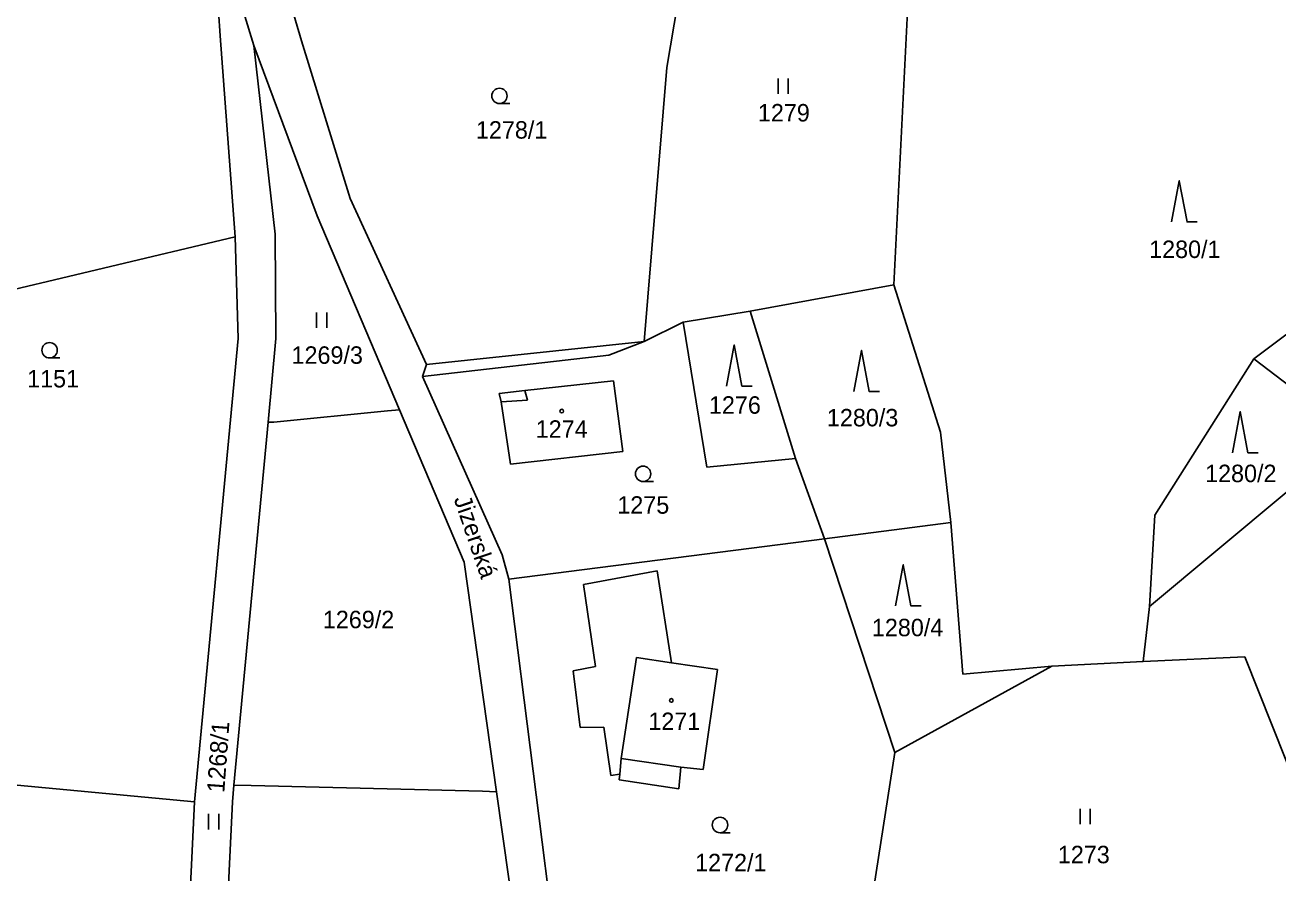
# Model space of a CAD drawing. Extents: x -670359 to -660124, y -978807 to -970072.
# Drawn here: x -670104.9 to -669982.9, y -977942.9 to -977860.3 of the extents above; entities that cross this region are included whole.
import ezdxf

# ---------------------------------------------------------------- set-up
doc = ezdxf.new("R2010")
doc.units = 0
for name, color, linetype in [('Hranice parcel', 7, 'Continuous'), ('Parcelní čísla', 7, 'Continuous'), ('Pop  PČ popisy', 7, 'Continuous'), ('Vnitřní kresba', 7, 'Continuous'), ('Značky budov', 7, 'Continuous'), ('Značky kultur', 7, 'Continuous')]:
    doc.layers.add(name, color=color, linetype=linetype)

msp = doc.modelspace()

# ---------------------------------------------------------------- linework, layer by layer
at = {"layer": 'Hranice parcel'}
for points in [[(-670042.41, -977864.47), (-670039.24, -977845.65)], [(-670086.79, -977848.75), (-670082.65, -977862.31)], [(-670018.5, -977849.23), (-670020.31, -977885.6)], [(-670086.58, -977851.74), (-670085.93, -977861.38)], [(-670078.01, -977861.85), (-670080.34, -977853.91)], [(-670085.93, -977861.38), (-670084.47, -977880.95)], [(-670073.25, -977877.2), (-670078.01, -977861.85)], [(-670076.48, -977878.9), (-670082.65, -977862.31)], [(-670082.65, -977862.31), (-670080.55, -977880.68)], [(-670044.64, -977891.14), (-670042.41, -977864.47)], [(-670065.82, -977893.36), (-670073.25, -977877.2)], [(-670076.48, -977878.9), (-670068.45, -977897.78)], [(-669966.52, -977878.8), (-669985.24, -977892.82)], [(-670084.47, -977880.95), (-670084.18, -977890.85)], [(-670080.55, -977880.68), (-670080.5, -977890.83)], [(-670020.31, -977885.6), (-670034.29, -977888.16)], [(-670020.31, -977885.6), (-670015.77, -977899.95)], [(-670040.84, -977889.24), (-670034.29, -977888.16)], [(-670034.29, -977888.16), (-670029.89, -977902.52)], [(-670040.84, -977889.24), (-670044.64, -977891.14)], [(-670038.52, -977903.37), (-670040.84, -977889.24)], [(-670084.18, -977890.85), (-670088.41, -977935.95)], [(-670080.5, -977890.83), (-670081.26, -977898.98)], [(-670048.07, -977892.47), (-670044.64, -977891.14)], [(-670066.21, -977894.52), (-670048.07, -977892.47)], [(-670066.21, -977894.52), (-670065.82, -977893.36)], [(-669985.24, -977892.82), (-669994.91, -977908.03)], [(-669985.24, -977892.82), (-669975.44, -977900.27)], [(-670058.47, -977911.88), (-670066.21, -977894.52)], [(-670056.24, -977895.9), (-670047.61, -977894.95)], [(-670047.61, -977894.95), (-670046.69, -977901.82)], [(-670058.74, -977896.2), (-670056.24, -977895.9)], [(-670058.55, -977897.01), (-670058.74, -977896.2)], [(-670057.64, -977903.08), (-670058.55, -977897.01)], [(-670080.69, -977898.97), (-670069.61, -977897.89)], [(-670069.61, -977897.89), (-670068.45, -977897.78)], [(-670062.15, -977912.62), (-670068.45, -977897.78)], [(-670081.26, -977898.98), (-670084.58, -977934.32)], [(-670081.26, -977898.98), (-670080.69, -977898.97)], [(-670015.77, -977899.95), (-670014.77, -977908.76)], [(-669975.44, -977900.27), (-669995.43, -977916.93)], [(-670046.69, -977901.82), (-670057.64, -977903.08)], [(-670029.89, -977902.52), (-670038.52, -977903.37)], [(-670029.89, -977902.52), (-670027.05, -977910.33)], [(-669994.91, -977908.03), (-669995.43, -977916.93)], [(-670027.05, -977910.33), (-670014.77, -977908.76)], [(-670014.77, -977908.76), (-670013.58, -977923.51)], [(-670057.82, -977914.27), (-670027.05, -977910.33)], [(-670027.05, -977910.33), (-670020.22, -977931.15)], [(-670057.82, -977914.27), (-670058.47, -977911.88)], [(-670062.15, -977912.62), (-670059, -977934.95)], [(-670050.54, -977914.79), (-670043.35, -977913.46)], [(-670043.35, -977913.46), (-670041.95, -977922.4)], [(-670053.06, -977951.64), (-670057.82, -977914.27)], [(-670049.38, -977922.77), (-670050.54, -977914.79)], [(-669995.43, -977916.93), (-669996.04, -977922.29)], [(-669996.04, -977922.29), (-669986.12, -977921.83)], [(-669986.12, -977921.83), (-669974.21, -977951.73)], [(-670051.53, -977923.18), (-670049.38, -977922.77)], [(-670050.86, -977928.69), (-670051.53, -977923.18)], [(-670041.95, -977922.4), (-670037.48, -977923.06)], [(-670037.48, -977923.06), (-670038.89, -977932.8)], [(-670020.22, -977931.15), (-670004.91, -977922.74)], [(-670013.58, -977923.51), (-670004.91, -977922.74)], [(-670004.91, -977922.74), (-669996.04, -977922.29)], [(-670048.54, -977928.68), (-670050.86, -977928.69)], [(-670047.88, -977933.39), (-670048.54, -977928.68)], [(-670020.22, -977931.15), (-670023.9, -977954.91)], [(-670041.04, -977932.57), (-670041.25, -977934.67)], [(-670038.89, -977932.8), (-670041.04, -977932.57)], [(-670119.19, -977933.05), (-670088.41, -977935.95)], [(-670047.88, -977933.39), (-670047.01, -977933.23)], [(-670047.06, -977933.81), (-670047.01, -977933.23)], [(-670041.25, -977934.67), (-670047.06, -977933.81)], [(-670084.73, -977935.93), (-670084.58, -977934.32)], [(-670084.58, -977934.32), (-670082.89, -977934.36)], [(-670082.89, -977934.36), (-670060.37, -977934.91)], [(-670060.37, -977934.91), (-670059, -977934.95)], [(-670056.57, -977952.14), (-670059, -977934.95)], [(-670088.41, -977935.95), (-670089.06, -977949.54)], [(-670084.73, -977935.93), (-670087.67, -977997.06)]]:
    msp.add_lwpolyline(points, dxfattribs=at)
at = {"layer": 'Vnitřní kresba'}
for points in [[(-670122.96, -977890.08), (-670084.47, -977880.95)], [(-670044.64, -977891.14), (-670065.82, -977893.36)], [(-670056, -977896.85), (-670056.24, -977895.9)], [(-670058.55, -977897.01), (-670056, -977896.85)], [(-670045.37, -977921.9), (-670046.88, -977931.72)], [(-670045.37, -977921.9), (-670041.95, -977922.4)], [(-670046.88, -977931.72), (-670047.01, -977933.23)], [(-670041.04, -977932.57), (-670046.88, -977931.72)]]:
    msp.add_lwpolyline(points, dxfattribs=at)
at = {"layer": 'Značky budov'}
for centre in [(-670052.65, -977897.9), (-670041.98, -977926.07)]:
    msp.add_circle(centre, 0.175, dxfattribs=at)
at = {"layer": 'Značky kultur'}
for p, q in [((-670031.59, -977865.51), (-670031.59, -977867.01)), ((-670030.59, -977867.01), (-670030.59, -977865.51)), ((-670058.72, -977867.97), (-670057.72, -977867.97)), ((-670076.53, -977888.3), (-670076.53, -977889.8)), ((-670075.53, -977889.8), (-670075.53, -977888.3)), ((-670102.53, -977892.73), (-670101.53, -977892.73)), ((-670044.73, -977904.76), (-670043.73, -977904.76)), ((-670002.18, -977936.62), (-670002.18, -977938.12)), ((-670001.18, -977938.12), (-670001.18, -977936.62)), ((-670087.05, -977937.12), (-670087.05, -977938.62)), ((-670086.05, -977938.62), (-670086.05, -977937.12)), ((-670037.24, -977938.94), (-670036.24, -977938.94))]:
    msp.add_line(p, q, dxfattribs=at)
for points in [[(-669993.26, -977879.48), (-669992.51, -977875.48), (-669991.76, -977879.48), (-669990.76, -977879.48)], [(-670036.61, -977895.46), (-670035.86, -977891.46), (-670035.11, -977895.46), (-670034.11, -977895.46)], [(-670024.21, -977896), (-670023.46, -977892), (-670022.71, -977896), (-670021.71, -977896)], [(-669987.33, -977901.95), (-669986.58, -977897.95), (-669985.83, -977901.95), (-669984.83, -977901.95)], [(-670020.15, -977916.86), (-670019.4, -977912.86), (-670018.65, -977916.86), (-670017.65, -977916.86)]]:
    msp.add_lwpolyline(points, dxfattribs=at)
for centre, radius in [((-670058.72, -977867.22), 0.75), ((-670102.53, -977891.98), 0.75), ((-670052.65, -977897.9), 0.175), ((-670044.73, -977904.01), 0.75), ((-670041.98, -977926.07), 0.175), ((-670037.24, -977938.19), 0.75)]:
    msp.add_circle(centre, radius, dxfattribs=at)

# ---------------------------------------------------------------- texts
at = {"layer": 'Parcelní čísla'}
for s, p in [('1279', (-670033.55, -977869.71)), ('1278/1', (-670061.01, -977871.38)), ('1280/1', (-669995.45, -977883)), ('1269/3', (-670078.97, -977893.3)), ('1151', (-670104.72, -977895.6)), ('1276', (-670038.32, -977898.16)), ('1280/3', (-670026.83, -977899.39)), ('1274', (-670055.19, -977900.5)), ('1280/2', (-669990, -977904.82)), ('1275', (-670047.24, -977907.89)), ('1269/2', (-670075.92, -977919.04)), ('1280/4', (-670022.45, -977919.82)), ('1271', (-670044.22, -977928.95)), ('1273', (-670004.34, -977941.92)), ('1272/1', (-670039.67, -977942.7))]:
    msp.add_text(s, height=1.7, dxfattribs=at).set_placement(p)
msp.add_text('1268/1', height=1.7, rotation=85.7947, dxfattribs=at).set_placement((-670085.52, -977935.09))
at = {"layer": 'Pop  PČ popisy'}
msp.add_text('Jizerská', height=1.7, rotation=288.8934, dxfattribs=at).set_placement((-670063.19, -977906.45))

doc.saveas('drawing.dxf')
